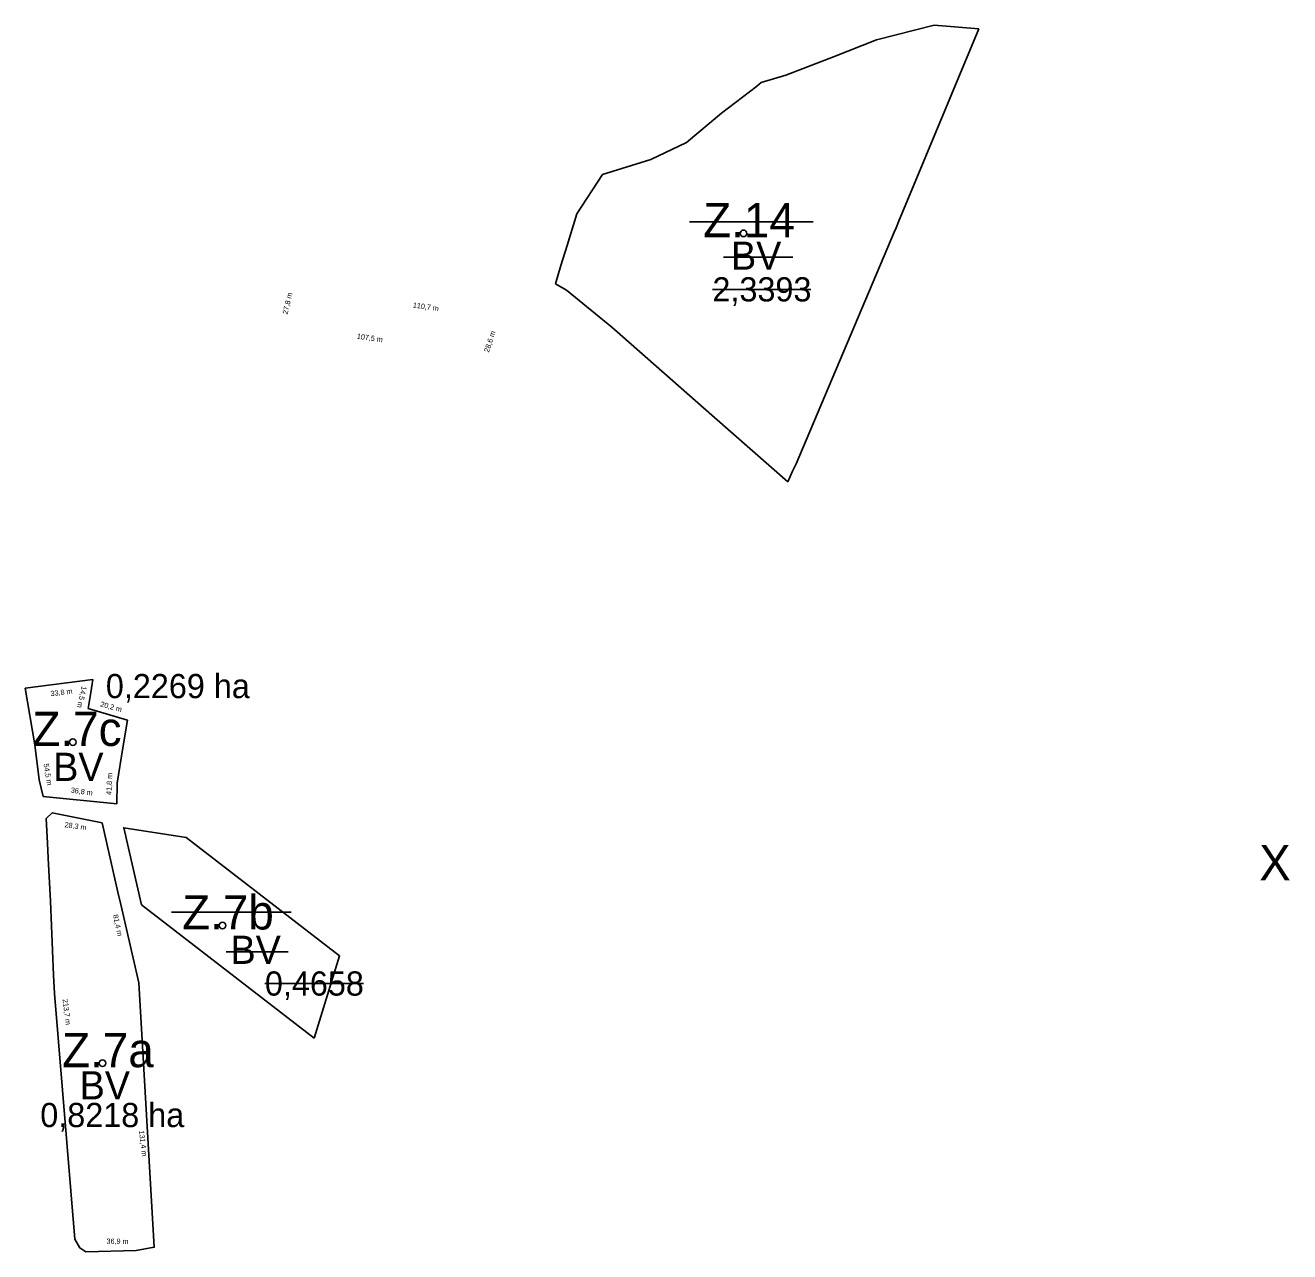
# Model space of a CAD drawing. Extents: x -554894 to -553703, y -1185789 to -1185042.
# Drawn here: x -554330 to -553703, y -1185789 to -1185180 of the extents above; entities that cross this region are included whole.
import ezdxf

# ---------------------------------------------------------------- set-up
doc = ezdxf.new("R2010")
doc.units = 0
for name, color, linetype in [('BILA_TECKA', 7, 'Continuous'), ('ID_navrh', 7, 'Continuous'), ('KRIZEK_ke_zruseni', 7, 'Continuous'), ('LEG_prac_vykres_ZPF', 7, 'Continuous'), ('navrh_BV', 7, 'Continuous'), ('OBRYS_PLOCH', 7, 'Continuous'), ('REGULATIV_navrh', 7, 'Continuous'), ('upusteno_platny_UP', 7, 'Continuous'), ('upusteno_zmena_1', 7, 'Continuous'), ('vymery', 7, 'Continuous'), ('ZASTAVITELNA_PLOCHA', 7, 'Continuous')]:
    doc.layers.add(name, color=color, linetype=linetype)

msp = doc.modelspace()

# ---------------------------------------------------------------- linework, layer by layer
at = {"layer": 'BILA_TECKA'}
for centre in [(-553974.12, -1185283.45), (-554306.72, -1185535.81), (-554232.46, -1185626.81), (-554291.97, -1185695.11), (-554291.97, -1185695.11)]:
    msp.add_circle(centre, 1.64, dxfattribs=at)
at = {"layer": 'KRIZEK_ke_zruseni'}
for p, q in [((-554000.97, -1185277.73), (-553939.52, -1185277.73)), ((-553984.08, -1185295.25), (-553949.65, -1185295.25)), ((-554198.44, -1185620.15), (-554257.83, -1185620.15)), ((-554230.7, -1185639.91), (-554199.85, -1185639.91))]:
    msp.add_line(p, q, dxfattribs=at)
at = {"layer": 'navrh_BV'}
for p, q in [((-554296.7, -1185504.81), (-554330.26, -1185509)), ((-554296.7, -1185504.81), (-554330.26, -1185509)), ((-554297.73, -1185511.18), (-554296.7, -1185504.81)), ((-554297.73, -1185511.18), (-554296.7, -1185504.81)), ((-554330.26, -1185509), (-554325.54, -1185537.09)), ((-554330.26, -1185509), (-554325.54, -1185537.09)), ((-554299.01, -1185519.14), (-554297.73, -1185511.18)), ((-554299.01, -1185519.14), (-554297.73, -1185511.18)), ((-554279.64, -1185524.91), (-554299.01, -1185519.14)), ((-554279.64, -1185524.91), (-554299.01, -1185519.14)), ((-554281.87, -1185538.72), (-554279.64, -1185524.91)), ((-554281.87, -1185538.72), (-554279.64, -1185524.91)), ((-554325.54, -1185537.09), (-554323.36, -1185554.5)), ((-554325.54, -1185537.09), (-554323.36, -1185554.5)), ((-554284.68, -1185556.1), (-554281.87, -1185538.72)), ((-554284.68, -1185556.1), (-554281.87, -1185538.72)), ((-554323.36, -1185554.5), (-554321.47, -1185562.78)), ((-554323.36, -1185554.5), (-554321.47, -1185562.78)), ((-554284.82, -1185566.4), (-554284.68, -1185556.1)), ((-554284.82, -1185566.4), (-554284.68, -1185556.1)), ((-554321.47, -1185562.78), (-554286.52, -1185566.23)), ((-554321.47, -1185562.78), (-554286.52, -1185566.23)), ((-554286.52, -1185566.23), (-554284.82, -1185566.4)), ((-554286.52, -1185566.23), (-554284.82, -1185566.4))]:
    msp.add_line(p, q, dxfattribs=at)
msp.add_lwpolyline([(-554305.65, -1185782.36), (-554303.28, -1185786.68), (-554300.2, -1185788.59), (-554275.27, -1185787.98), (-554266.32, -1185786.4), (-554273.88, -1185655.23), (-554282.43, -1185618.58), (-554282.94, -1185616.37), (-554284.34, -1185610.24), (-554292.21, -1185575.92), (-554316.87, -1185570.9), (-554319.85, -1185573.67), (-554319.21, -1185586), (-554318.84, -1185593.32), (-554317.73, -1185614.65), (-554316.26, -1185651.34), (-554315.85, -1185660.44), (-554305.65, -1185782.36)], dxfattribs=at)
at = {"layer": 'OBRYS_PLOCH'}
for p, q in [((-554296.7, -1185504.81), (-554330.26, -1185509)), ((-554297.73, -1185511.18), (-554296.7, -1185504.81)), ((-554330.26, -1185509), (-554325.54, -1185537.09)), ((-554299.01, -1185519.14), (-554297.73, -1185511.18)), ((-554279.64, -1185524.91), (-554299.01, -1185519.14)), ((-554281.87, -1185538.72), (-554279.64, -1185524.91)), ((-554325.54, -1185537.09), (-554323.36, -1185554.5)), ((-554284.68, -1185556.1), (-554281.87, -1185538.72)), ((-554323.36, -1185554.5), (-554321.47, -1185562.78)), ((-554284.82, -1185566.4), (-554284.68, -1185556.1)), ((-554321.47, -1185562.78), (-554286.52, -1185566.23)), ((-554286.52, -1185566.23), (-554284.82, -1185566.4)), ((-554273.88, -1185655.23), (-554282.43, -1185618.58)), ((-554266.32, -1185786.4), (-554273.88, -1185655.23))]:
    msp.add_line(p, q, dxfattribs=at)
for points in [[(-554292.21, -1185575.92), (-554316.87, -1185570.9), (-554319.85, -1185573.67), (-554319.21, -1185586)], [(-554282.43, -1185618.58), (-554282.94, -1185616.37), (-554284.34, -1185610.24), (-554292.21, -1185575.92)], [(-554319.21, -1185586), (-554318.84, -1185593.32), (-554317.73, -1185614.65), (-554316.26, -1185651.34)], [(-554316.26, -1185651.34), (-554315.85, -1185660.44), (-554305.65, -1185782.36)], [(-554305.65, -1185782.36), (-554303.28, -1185786.68), (-554300.2, -1185788.59), (-554275.27, -1185787.98), (-554266.32, -1185786.4)]]:
    msp.add_lwpolyline(points, dxfattribs=at)
at = {"layer": 'upusteno_platny_UP'}
for points in [[(-554250.48, -1185583.07), (-554281.41, -1185578.27), (-554272.65, -1185616.49), (-554187.01, -1185682.72)], [(-554187.01, -1185682.72), (-554174.43, -1185641.89), (-554250.48, -1185583.07)]]:
    msp.add_lwpolyline(points, dxfattribs=at)
at = {"layer": 'upusteno_zmena_1'}
for p, q in [((-553879.62, -1185180.24), (-553908.21, -1185187.44)), ((-553897.27, -1185277.81), (-553857.41, -1185182)), ((-553857.41, -1185182), (-553879.62, -1185180.24)), ((-553908.21, -1185187.44), (-553929.57, -1185195.95)), ((-553929.57, -1185195.95), (-553953.2, -1185204.97)), ((-553953.2, -1185204.97), (-553965.29, -1185208.64)), ((-553967.75, -1185210.53), (-553985.07, -1185223.8)), ((-553965.29, -1185208.64), (-553967.75, -1185210.53)), ((-553985.07, -1185223.8), (-554002.44, -1185238.44)), ((-554002.44, -1185238.44), (-554020.12, -1185246.87)), ((-554020.12, -1185246.87), (-554044.05, -1185254.33)), ((-553898.47, -1185280.64), (-553897.27, -1185277.81)), ((-553948.08, -1185397.72), (-553899.43, -1185282.92)), ((-553899.43, -1185282.92), (-553898.47, -1185280.64)), ((-554061.58, -1185289.53), (-554064.64, -1185299.47)), ((-554064.64, -1185299.47), (-554067.41, -1185308.49)), ((-554067.41, -1185308.49), (-554061.83, -1185311.61)), ((-554061.83, -1185311.61), (-554039.47, -1185330.02)), ((-554039.47, -1185330.02), (-553988.56, -1185374.87)), ((-553988.56, -1185374.87), (-553952.14, -1185406.78)), ((-553949.75, -1185401.45), (-553948.08, -1185397.72)), ((-553952.14, -1185406.78), (-553949.75, -1185401.45))]:
    msp.add_line(p, q, dxfattribs=at)
msp.add_lwpolyline([(-554044.05, -1185254.33), (-554056.72, -1185273.74), (-554061.58, -1185289.53)], dxfattribs=at)
at = {"layer": 'vymery'}
for p, q in [((-553989.52, -1185311.22), (-553940.67, -1185311.22)), ((-554211.46, -1185655.55), (-554162.61, -1185655.55))]:
    msp.add_line(p, q, dxfattribs=at)
at = {"layer": 'ZASTAVITELNA_PLOCHA'}
for p, q in [((-554296.7, -1185504.81), (-554330.26, -1185509)), ((-554297.73, -1185511.18), (-554296.7, -1185504.81)), ((-554330.26, -1185509), (-554325.54, -1185537.09)), ((-554299.01, -1185519.14), (-554297.73, -1185511.18)), ((-554279.64, -1185524.91), (-554299.01, -1185519.14)), ((-554281.87, -1185538.72), (-554279.64, -1185524.91)), ((-554325.54, -1185537.09), (-554323.36, -1185554.5)), ((-554284.68, -1185556.1), (-554281.87, -1185538.72)), ((-554323.36, -1185554.5), (-554321.47, -1185562.78)), ((-554284.82, -1185566.4), (-554284.68, -1185556.1)), ((-554321.47, -1185562.78), (-554286.52, -1185566.23)), ((-554286.52, -1185566.23), (-554284.82, -1185566.4))]:
    msp.add_line(p, q, dxfattribs=at)
msp.add_lwpolyline([(-554305.65, -1185782.36), (-554303.28, -1185786.68), (-554300.2, -1185788.59), (-554275.27, -1185787.98), (-554266.32, -1185786.4), (-554273.88, -1185655.23), (-554282.43, -1185618.58), (-554282.94, -1185616.37), (-554284.34, -1185610.24), (-554292.21, -1185575.92), (-554316.87, -1185570.9), (-554319.85, -1185573.67), (-554319.21, -1185586), (-554318.84, -1185593.32), (-554317.73, -1185614.65), (-554316.26, -1185651.34), (-554315.85, -1185660.44), (-554305.65, -1185782.36)], dxfattribs=at)

# ---------------------------------------------------------------- texts
at = {"layer": 'ID_navrh'}
for s, p in [('Z.14', (-553994.14, -1185285.38)), ('Z.7c', (-554326.74, -1185537.74)), ('Z.7b', (-554252.51, -1185628.75)), ('Z.7a', (-554312.02, -1185697.05)), ('Z.7a', (-554312.02, -1185697.05))]:
    msp.add_text(s, height=17, dxfattribs=at).set_placement(p)
at = {"layer": 'LEG_prac_vykres_ZPF'}
msp.add_text('X', height=17.5, dxfattribs=at).set_placement((-553718.39, -1185604.37))
at = {"layer": 'REGULATIV_navrh'}
for p in [(-553980.32, -1185301.51), (-554316.42, -1185555.09), (-554228.51, -1185645.83), (-554303.3, -1185713.04), (-554303.3, -1185713.04)]:
    msp.add_text('BV', height=14, dxfattribs=at).set_placement(p)
at = {"layer": 'vymery'}
for s, p in [('2,3393', (-553989.52, -1185317.22)), ('0,2269 ha', (-554290.31, -1185514.01)), ('0,4658', (-554211.46, -1185661.55)), ('0,8218 ha', (-554322.83, -1185726.78))]:
    msp.add_text(s, height=12, dxfattribs=at).set_placement(p)
for s, rotation, p in [('27,8 m', 77.26189, (-554200.21, -1185323.81)), ('110,7 m', 351.95053, (-554138.2, -1185320.21)), ('107,5 m', 351.95053, (-554165.98, -1185335.69)), ('28,6 m', 71.81606, (-554100.42, -1185342.7)), ('33,8 m', 6.71137, (-554317.61, -1185513.05)), ('14,5 m', 257.4552, (-554302.25, -1185507.85)), ('20,2 m', 344.76298, (-554293.27, -1185518.07)), ('54,5 m', 279.37619, (-554321.2, -1185546.66)), ('41,8 m', 87.45145, (-554287.58, -1185562.07)), ('36,8 m', 351.95053, (-554307.84, -1185560.81)), ('28,3 m', 351.95053, (-554310.91, -1185577.97)), ('81,4 m', 282.47976, (-554286.84, -1185621.6)), ('213,7 m', 277.01441, (-554311.76, -1185663.37)), ('131,4 m', 277.01441, (-554273.94, -1185728.63)), ('36,9 m', 359.54864, (-554290, -1185784.64))]:
    msp.add_text(s, height=2.592, rotation=rotation, dxfattribs=at).set_placement(p)

doc.saveas('drawing.dxf')
